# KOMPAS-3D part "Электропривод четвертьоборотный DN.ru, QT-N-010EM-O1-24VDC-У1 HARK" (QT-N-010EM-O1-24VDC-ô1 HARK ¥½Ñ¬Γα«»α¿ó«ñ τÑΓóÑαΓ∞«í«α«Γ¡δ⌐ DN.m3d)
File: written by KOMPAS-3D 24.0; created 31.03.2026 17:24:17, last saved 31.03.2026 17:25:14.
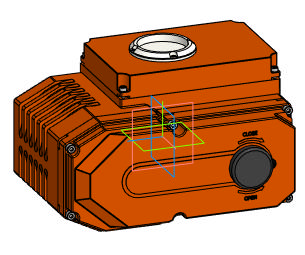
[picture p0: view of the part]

Document properties: Автор: DN.RU; Полное имя файла: D:\PROJECT CAD\DN.RU\...195\Исходники\24В\QT-N-010EM-O1-24VDC-У1 HARK Электропривод четвертьоборотный DN.ru\QT-N-010EM-O1-24VDC-У1 HARK Электропривод четвертьоборотный DN.m3d

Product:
- Body: Твердое тело1  | qty 1
    Масса: 18.642153
- Part/product: Электропривод четвертьоборотный DN.ru  | designation QT-N-010EM-O1-24VDC-У1 HARK
    Масса: 4.6
    Раздел спецификации: Прочие изделия
    Комментарий: D300-14484
    Примечание: D300-14485
    additional columns: Сталь

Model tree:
1. Твердое тело1  (labels: Твердое тело1)

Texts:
  QT-N-010EM-O1-24VDC-У1 HARK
